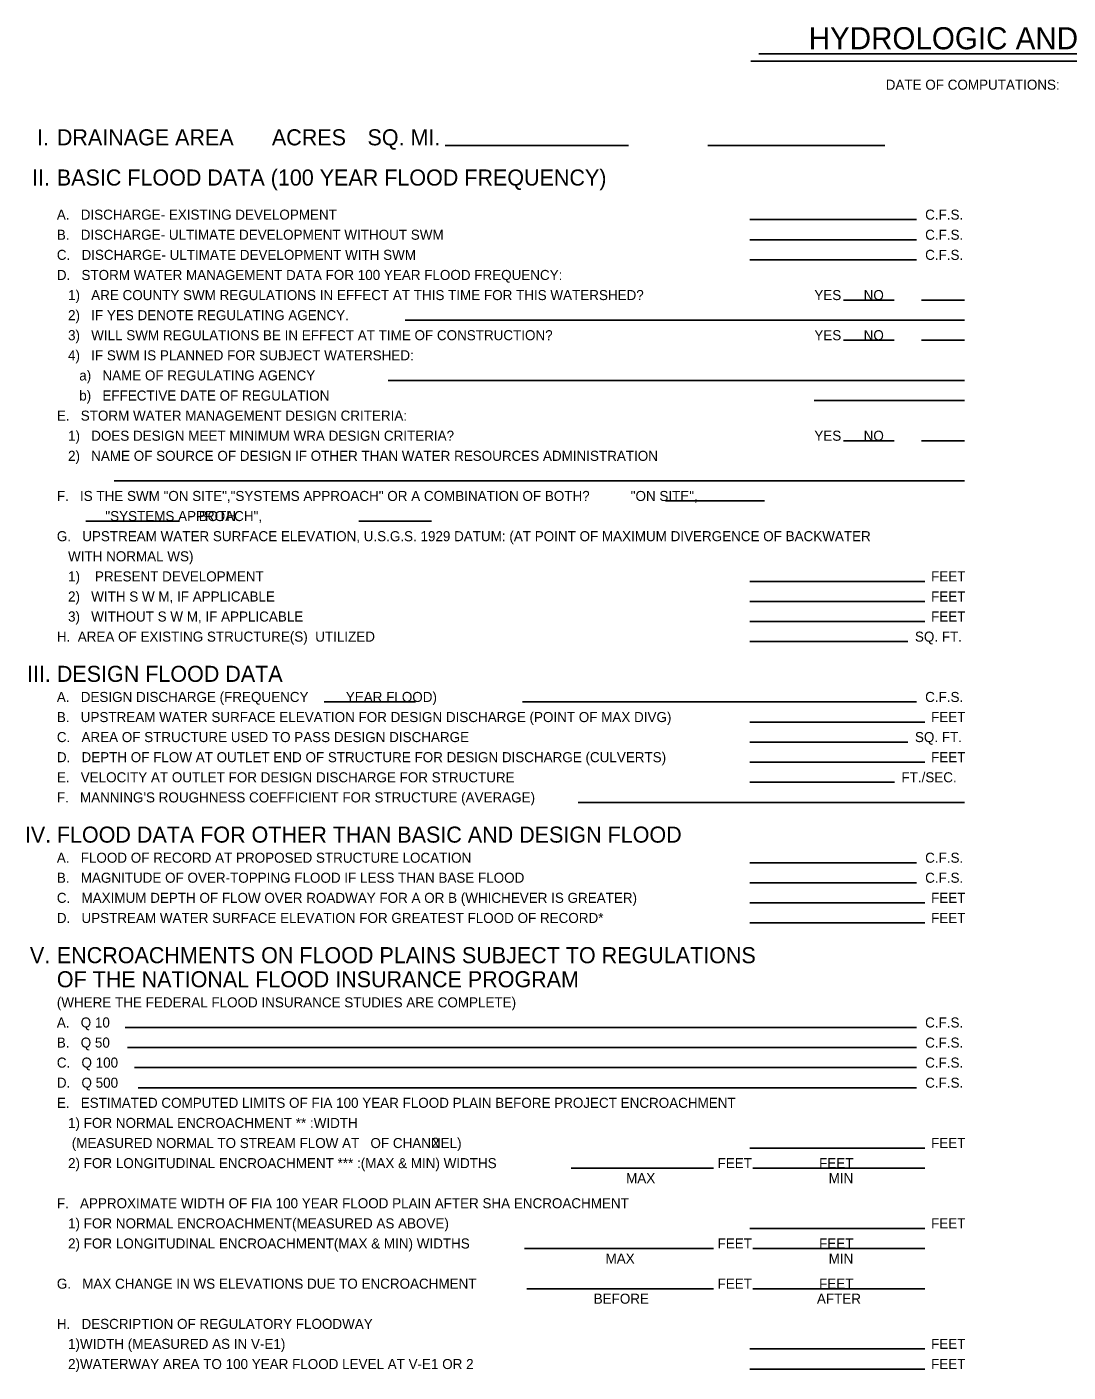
# Model space of a CAD drawing. Extents: x 3 to 31.3, y 2.1 to 20.5.
# Drawn here: x 3.01 to 13.21, y 7.36 to 20.53 of the extents above; entities that cross this region are included whole.
import ezdxf

# ---------------------------------------------------------------- set-up
doc = ezdxf.new("R2010")
doc.units = 0
doc.layers.add('GN-NOTE', color=7, linetype='Continuous')

msp = doc.modelspace()

# ---------------------------------------------------------------- linework, layer by layer
at = {"layer": 'GN-NOTE'}
for p, q in [((10.1, 20.198), (16.402, 20.198)), ((10.178, 20.27), (16.33, 20.27)), ((8.903, 19.374), (7.107, 19.374)), ((11.411, 19.374), (9.677, 19.374)), ((11.721, 18.646), (10.09, 18.646)), ((11.721, 18.449), (10.09, 18.449)), ((11.721, 18.252), (10.09, 18.252)), ((11.504, 17.858), (11.008, 17.858)), ((12.193, 17.858), (11.772, 17.858)), ((12.193, 17.661), (6.714, 17.661)), ((11.504, 17.465), (11.008, 17.465)), ((12.193, 17.465), (11.772, 17.465)), ((12.193, 17.071), (6.549, 17.071)), ((12.193, 16.874), (10.719, 16.874)), ((11.504, 16.48), (11.008, 16.48)), ((12.193, 16.48), (11.772, 16.48)), ((12.193, 16.087), (3.865, 16.087)), ((10.234, 15.89), (9.264, 15.89)), ((4.505, 15.693), (3.587, 15.693)), ((6.972, 15.693), (6.26, 15.693)), ((11.803, 15.102), (10.09, 15.102)), ((11.803, 14.905), (10.09, 14.905)), ((11.803, 14.709), (10.09, 14.709)), ((11.638, 14.512), (10.09, 14.512)), ((6.815, 13.921), (5.922, 13.921)), ((11.721, 13.921), (7.864, 13.921)), ((11.803, 13.724), (10.09, 13.724)), ((11.638, 13.528), (10.09, 13.528)), ((11.803, 13.331), (10.09, 13.331)), ((11.507, 13.134), (10.09, 13.134)), ((12.193, 12.937), (8.41, 12.937)), ((11.721, 12.346), (10.09, 12.346)), ((11.721, 12.15), (10.09, 12.15)), ((11.803, 11.953), (10.09, 11.953)), ((11.803, 11.756), (10.09, 11.756)), ((11.721, 10.732), (3.973, 10.732)), ((11.721, 10.535), (3.996, 10.535)), ((11.721, 10.339), (4.065, 10.339)), ((11.721, 10.142), (4.099, 10.142)), ((11.803, 9.551), (10.09, 9.551)), ((9.733, 9.354), (8.34, 9.354)), ((11.803, 9.354), (10.119, 9.354)), ((11.803, 8.764), (10.09, 8.764)), ((9.733, 8.567), (7.883, 8.567)), ((11.803, 8.567), (10.119, 8.567)), ((9.733, 8.173), (7.906, 8.173)), ((11.803, 8.173), (10.119, 8.173)), ((11.803, 7.583), (10.09, 7.583)), ((11.803, 7.386), (10.09, 7.386))]:
    msp.add_line(p, q, dxfattribs=at)

# ---------------------------------------------------------------- texts
for s, height, p in [('HYDROLOGIC AND HYDRAULIC DATA', 0.21654, (10.666, 20.315)), ('DATE OF COMPUTATIONS:', 0.09843, (11.421, 19.919)), ('I.  ', 0.1575, (3.108, 19.374)), ('DRAINAGE AREA', 0.15748, (3.303, 19.374)), ('                                    ACRES', 0.15748, (3.303, 19.374)), ('                                                    SQ. MI.', 0.15748, (3.303, 19.374)), ('II.  ', 0.1575, (3.059, 18.98)), ('BASIC FLOOD DATA (100 YEAR FLOOD FREQUENCY)', 0.15748, (3.303, 18.98)), ('A.   DISCHARGE- EXISTING DEVELOPMENT', 0.09843, (3.303, 18.646)), ('C.F.S.', 0.0984, (11.807, 18.646)), ('B.   DISCHARGE- ULTIMATE DEVELOPMENT WITHOUT SWM', 0.09843, (3.303, 18.449)), ('C.F.S.', 0.0984, (11.807, 18.449)), ('C.   DISCHARGE- ULTIMATE DEVELOPMENT WITH SWM', 0.09843, (3.303, 18.252)), ('C.F.S.', 0.0984, (11.807, 18.252)), ('D.   STORM WATER MANAGEMENT DATA FOR 100 YEAR FLOOD FREQUENCY:', 0.09843, (3.303, 18.055)), ('   1)   ARE COUNTY SWM REGULATIONS IN EFFECT AT THIS TIME FOR THIS WATERSHED?', 0.09843, (3.303, 17.858)), ('YES      NO     ', 0.09843, (10.722, 17.858)), ('   2)   IF YES DENOTE REGULATING AGENCY.', 0.09843, (3.303, 17.661)), ('   3)   WILL SWM REGULATIONS BE IN EFFECT AT TIME OF CONSTRUCTION?', 0.09843, (3.303, 17.465)), ('YES      NO     ', 0.09843, (10.722, 17.465)), ('   4)   IF SWM IS PLANNED FOR SUBJECT WATERSHED:', 0.09843, (3.303, 17.268)), ('      a)   NAME OF REGULATING AGENCY', 0.09843, (3.303, 17.071)), ('      b)   EFFECTIVE DATE OF REGULATION', 0.09843, (3.303, 16.874)), ('E.   STORM WATER MANAGEMENT DESIGN CRITERIA:', 0.09843, (3.303, 16.677)), ('   1)   DOES DESIGN MEET MINIMUM WRA DESIGN CRITERIA?', 0.09843, (3.303, 16.48)), ('YES      NO     ', 0.09843, (10.722, 16.48)), ('   2)   NAME OF SOURCE OF DESIGN IF OTHER THAN WATER RESOURCES ADMINISTRATION', 0.09843, (3.303, 16.283)), ('F.   IS THE SWM "ON SITE","SYSTEMS APPROACH" OR A COMBINATION OF BOTH?           "ON SITE",', 0.09843, (3.303, 15.89)), ('             "SYSTEMS APPROACH",', 0.09843, (3.303, 15.693)), ('                                      BOTH.', 0.09843, (3.303, 15.693)), ('G.   UPSTREAM WATER SURFACE ELEVATION, U.S.G.S. 1929 DATUM: (AT POINT OF MAXIMUM DIVERGENCE OF BACKWATER', 0.098425, (3.303, 15.496)), ('   WITH NORMAL WS)', 0.09843, (3.303, 15.299)), ('   1)    PRESENT DEVELOPMENT', 0.09843, (3.303, 15.102)), ('FEET', 0.0984, (11.865, 15.102)), ('   2)   WITH S W M, IF APPLICABLE', 0.09843, (3.303, 14.905)), ('FEET', 0.0984, (11.865, 14.905)), ('   3)   WITHOUT S W M, IF APPLICABLE', 0.09843, (3.303, 14.709)), ('FEET', 0.0984, (11.865, 14.709)), ('H.  AREA OF EXISTING STRUCTURE(S)  UTILIZED', 0.09843, (3.303, 14.512)), ('SQ. FT.', 0.0984, (11.707, 14.512)), ('III.  ', 0.1575, (3.01, 14.118)), ('DESIGN FLOOD DATA', 0.15748, (3.303, 14.118)), ('A.   DESIGN DISCHARGE (FREQUENCY          YEAR FLOOD)', 0.09843, (3.303, 13.921)), ('C.F.S.', 0.0984, (11.807, 13.921)), ('B.   UPSTREAM WATER SURFACE ELEVATION FOR DESIGN DISCHARGE (POINT OF MAX DIVG)', 0.09843, (3.303, 13.724)), ('FEET', 0.0984, (11.865, 13.724)), ('C.   AREA OF STRUCTURE USED TO PASS DESIGN DISCHARGE', 0.09843, (3.303, 13.528)), ('SQ. FT.', 0.0984, (11.707, 13.528)), ('D.   DEPTH OF FLOW AT OUTLET END OF STRUCTURE FOR DESIGN DISCHARGE (CULVERTS)', 0.09843, (3.303, 13.331)), ('FEET', 0.0984, (11.865, 13.331)), ('E.   VELOCITY AT OUTLET FOR DESIGN DISCHARGE FOR STRUCTURE', 0.09843, (3.303, 13.134)), ('FT./SEC.', 0.0984, (11.575, 13.134)), ("F.   MANNING'S ROUGHNESS COEFFICIENT FOR STRUCTURE (AVERAGE)", 0.09843, (3.303, 12.937)), ('IV.  ', 0.1575, (2.99, 12.543)), ('FLOOD DATA FOR OTHER THAN BASIC AND DESIGN FLOOD', 0.15748, (3.303, 12.543)), ('A.   FLOOD OF RECORD AT PROPOSED STRUCTURE LOCATION', 0.09843, (3.303, 12.346)), ('C.F.S.', 0.0984, (11.807, 12.346)), ('B.   MAGNITUDE OF OVER-TOPPING FLOOD IF LESS THAN BASE FLOOD', 0.09843, (3.303, 12.15)), ('C.F.S.', 0.0984, (11.807, 12.15)), ('C.   MAXIMUM DEPTH OF FLOW OVER ROADWAY FOR A OR B (WHICHEVER IS GREATER)', 0.09843, (3.303, 11.953)), ('FEET', 0.0984, (11.865, 11.953)), ('D.   UPSTREAM WATER SURFACE ELEVATION FOR GREATEST FLOOD OF RECORD*', 0.09843, (3.303, 11.756)), ('FEET', 0.0984, (11.865, 11.756)), ('V.  ', 0.1575, (3.039, 11.362)), ('ENCROACHMENTS ON FLOOD PLAINS SUBJECT TO REGULATIONS', 0.15748, (3.303, 11.362)), ('OF THE NATIONAL FLOOD INSURANCE PROGRAM', 0.15748, (3.303, 11.126)), ('(WHERE THE FEDERAL FLOOD INSURANCE STUDIES ARE COMPLETE)', 0.09843, (3.303, 10.929)), ('A.   Q 10', 0.0984, (3.303, 10.732)), ('C.F.S.', 0.0984, (11.807, 10.732)), ('B.   Q 50', 0.0984, (3.303, 10.535)), ('C.F.S.', 0.0984, (11.807, 10.535)), ('C.   Q 100', 0.0984, (3.303, 10.339)), ('C.F.S.', 0.0984, (11.807, 10.339)), ('D.   Q 500', 0.0984, (3.303, 10.142)), ('C.F.S.', 0.0984, (11.807, 10.142)), ('E.   ESTIMATED COMPUTED LIMITS OF FIA 100 YEAR FLOOD PLAIN BEFORE PROJECT ENCROACHMENT', 0.09843, (3.303, 9.945)), ('   1) FOR NORMAL ENCROACHMENT ** :WIDTH', 0.09843, (3.303, 9.748)), ('    (MEASURED NORMAL TO STREAM FLOW AT   OF CHANNEL)', 0.09843, (3.303, 9.551)), ('2', 0.0984, (6.974, 9.554)), ('FEET', 0.0984, (11.865, 9.551)), ('   2) FOR LONGITUDINAL ENCROACHMENT *** :(MAX & MIN) WIDTHS', 0.09843, (3.303, 9.354)), ('FEET                  FEET', 0.09843, (9.774, 9.354)), ('MAX', 0.0984, (8.878, 9.207)), ('MIN', 0.0984, (10.862, 9.207)), ('F.   APPROXIMATE WIDTH OF FIA 100 YEAR FLOOD PLAIN AFTER SHA ENCROACHMENT', 0.09843, (3.303, 8.961)), ('   1) FOR NORMAL ENCROACHMENT(MEASURED AS ABOVE)', 0.09843, (3.303, 8.764)), ('FEET', 0.0984, (11.865, 8.764)), ('   2) FOR LONGITUDINAL ENCROACHMENT(MAX & MIN) WIDTHS', 0.09843, (3.303, 8.567)), ('FEET                  FEET', 0.09843, (9.774, 8.567)), ('MAX', 0.0984, (8.677, 8.419)), ('MIN', 0.0984, (10.862, 8.419)), ('G.   MAX CHANGE IN WS ELEVATIONS DUE TO ENCROACHMENT', 0.09843, (3.303, 8.173)), ('FEET                  FEET', 0.09843, (9.774, 8.173)), ('BEFORE', 0.0984, (8.561, 8.026)), ('AFTER', 0.0984, (10.747, 8.026)), ('H.   DESCRIPTION OF REGULATORY FLOODWAY', 0.09843, (3.303, 7.779)), ('   1)WIDTH (MEASURED AS IN V-E1)', 0.09843, (3.303, 7.583)), ('FEET', 0.0984, (11.865, 7.583)), ('   2)WATERWAY AREA TO 100 YEAR FLOOD LEVEL AT V-E1 OR 2', 0.09843, (3.303, 7.386)), ('FEET', 0.0984, (11.865, 7.386))]:
    msp.add_text(s, height=height, dxfattribs=at).set_placement(p)

doc.saveas('drawing.dxf')
